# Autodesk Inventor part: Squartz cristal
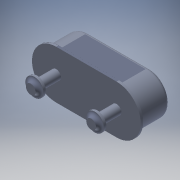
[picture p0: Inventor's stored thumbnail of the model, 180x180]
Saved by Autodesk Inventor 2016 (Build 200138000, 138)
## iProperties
Created: 2018-03
Part Number: Squartz cristal
Material: Générique
Document SubType Name: Modeling
Designer: Bruno
Density: 1 g/cm^3
Appearance: Par défaut
Author: Bruno
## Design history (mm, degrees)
feature "Composite1"
body "Srf1"
